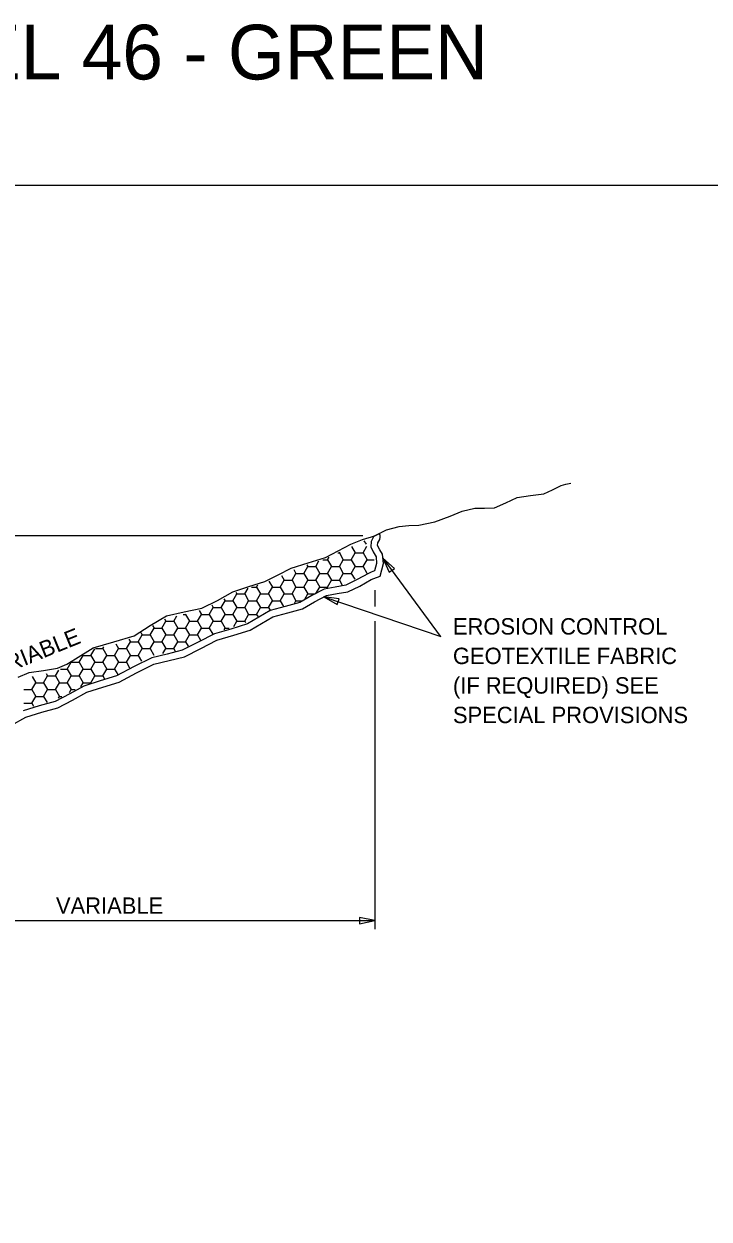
# Model space of a CAD drawing. Extents: x -439.1 to -407.9, y -458.1 to -436.2.
# Drawn here: x -424.75 to -418.48, y -447.12 to -436.2 of the extents above; entities that cross this region are included whole.
import ezdxf

# ---------------------------------------------------------------- set-up
doc = ezdxf.new("R2010")
doc.units = 0
for name, color, linetype in [('Default', 7, 'Continuous'), ('Draft_Named_Boundary', 7, 'Continuous'), ('Level 46', 7, 'Continuous')]:
    doc.layers.add(name, color=color, linetype=linetype)

msp = doc.modelspace()

# ---------------------------------------------------------------- linework, layer by layer
at = {"layer": 'Default'}
for p, q in [((-421.646, -440.877), (-427.407, -440.877)), ((-421.537, -440.877), (-421.544, -440.879)), ((-421.493, -440.855), (-421.537, -440.877)), ((-421.749, -440.976), (-421.715, -441.033)), ((-421.643, -441.033), (-421.608, -440.973)), ((-421.635, -440.923), (-421.616, -440.955)), ((-422.076, -441.158), (-422.047, -441.107)), ((-422.012, -441.096), (-421.968, -441.096)), ((-421.968, -441.096), (-421.954, -441.071)), ((-421.968, -441.096), (-421.932, -441.158)), ((-421.873, -441.033), (-421.86, -441.033)), ((-421.86, -441.033), (-421.855, -441.025)), ((-421.86, -441.033), (-421.824, -441.096)), ((-421.86, -441.158), (-421.824, -441.096)), ((-421.824, -441.096), (-421.752, -441.096)), ((-421.752, -441.096), (-421.715, -441.033)), ((-421.752, -441.096), (-421.715, -441.158)), ((-421.715, -441.033), (-421.643, -441.033)), ((-421.643, -441.033), (-421.607, -441.096)), ((-421.643, -441.158), (-421.607, -441.096)), ((-421.607, -441.096), (-421.541, -441.096)), ((-421.461, -441.081), (-420.937, -441.794)), ((-422.293, -441.283), (-422.257, -441.221)), ((-422.277, -441.186), (-422.257, -441.221)), ((-422.257, -441.221), (-422.185, -441.221)), ((-422.185, -441.221), (-422.148, -441.158)), ((-422.185, -441.221), (-422.148, -441.283)), ((-422.157, -441.144), (-422.148, -441.158)), ((-422.148, -441.158), (-422.076, -441.158)), ((-422.076, -441.158), (-422.04, -441.221)), ((-422.076, -441.283), (-422.04, -441.221)), ((-422.04, -441.221), (-421.968, -441.221)), ((-421.968, -441.221), (-421.932, -441.158)), ((-421.968, -441.221), (-421.932, -441.283)), ((-421.932, -441.158), (-421.86, -441.158)), ((-421.86, -441.158), (-421.824, -441.221)), ((-421.86, -441.283), (-421.824, -441.221)), ((-421.824, -441.221), (-421.752, -441.221)), ((-421.752, -441.221), (-421.715, -441.158)), ((-421.752, -441.221), (-421.72, -441.275)), ((-421.715, -441.158), (-421.643, -441.158)), ((-421.643, -441.158), (-421.608, -441.219)), ((-422.618, -441.346), (-422.606, -441.326)), ((-422.504, -441.292), (-422.473, -441.346)), ((-422.401, -441.346), (-422.365, -441.283)), ((-422.39, -441.24), (-422.365, -441.283)), ((-422.365, -441.283), (-422.293, -441.283)), ((-422.293, -441.283), (-422.257, -441.346)), ((-422.185, -441.346), (-422.148, -441.283)), ((-422.148, -441.283), (-422.076, -441.283)), ((-422.076, -441.283), (-422.04, -441.346)), ((-421.968, -441.346), (-421.932, -441.283)), ((-421.932, -441.283), (-421.86, -441.283)), ((-421.86, -441.283), (-421.834, -441.328)), ((-422.834, -441.471), (-422.798, -441.408)), ((-422.806, -441.394), (-422.798, -441.408)), ((-422.798, -441.408), (-422.726, -441.408)), ((-422.726, -441.408), (-422.696, -441.356)), ((-422.726, -441.408), (-422.69, -441.471)), ((-422.664, -441.346), (-422.618, -441.346)), ((-422.618, -441.346), (-422.581, -441.408)), ((-422.618, -441.471), (-422.581, -441.408)), ((-422.581, -441.408), (-422.509, -441.408)), ((-422.509, -441.408), (-422.473, -441.346)), ((-422.509, -441.408), (-422.473, -441.471)), ((-422.473, -441.346), (-422.401, -441.346)), ((-422.401, -441.346), (-422.365, -441.408)), ((-422.401, -441.471), (-422.365, -441.408)), ((-422.365, -441.408), (-422.293, -441.408)), ((-422.293, -441.408), (-422.257, -441.346)), ((-422.293, -441.408), (-422.257, -441.471)), ((-422.257, -441.346), (-422.185, -441.346)), ((-422.185, -441.346), (-422.148, -441.408)), ((-422.177, -441.457), (-422.148, -441.408)), ((-422.148, -441.408), (-422.08, -441.408)), ((-422.075, -441.406), (-422.04, -441.346)), ((-422.04, -441.346), (-421.968, -441.346)), ((-422.001, -441.435), (-420.932, -441.798)), ((-421.968, -441.346), (-421.965, -441.35)), ((-421.537, -441.373), (-421.537, -441.524)), ((-423.051, -441.596), (-423.015, -441.533)), ((-423.028, -441.509), (-423.015, -441.533)), ((-423.015, -441.533), (-422.942, -441.533)), ((-422.942, -441.533), (-422.906, -441.471)), ((-422.942, -441.533), (-422.906, -441.596)), ((-422.917, -441.452), (-422.906, -441.471)), ((-422.906, -441.471), (-422.834, -441.471)), ((-422.834, -441.471), (-422.798, -441.533)), ((-422.834, -441.596), (-422.798, -441.533)), ((-422.798, -441.533), (-422.726, -441.533)), ((-422.726, -441.533), (-422.69, -441.471)), ((-422.726, -441.533), (-422.69, -441.596)), ((-422.69, -441.471), (-422.618, -441.471)), ((-422.618, -441.471), (-422.581, -441.533)), ((-422.618, -441.596), (-422.581, -441.533)), ((-422.581, -441.533), (-422.509, -441.533)), ((-422.509, -441.533), (-422.473, -441.471)), ((-422.509, -441.533), (-422.491, -441.564)), ((-422.473, -441.471), (-422.401, -441.471)), ((-422.401, -441.471), (-422.37, -441.525)), ((-422.271, -441.496), (-422.257, -441.471)), ((-422.257, -441.471), (-422.204, -441.471)), ((-423.484, -441.721), (-423.448, -441.658)), ((-423.46, -441.637), (-423.448, -441.658)), ((-423.448, -441.658), (-423.375, -441.658)), ((-423.375, -441.658), (-423.347, -441.609)), ((-423.375, -441.658), (-423.339, -441.721)), ((-423.29, -441.596), (-423.267, -441.596)), ((-423.267, -441.596), (-423.264, -441.59)), ((-423.267, -441.596), (-423.231, -441.658)), ((-423.267, -441.721), (-423.231, -441.658)), ((-423.231, -441.658), (-423.159, -441.658)), ((-423.159, -441.658), (-423.123, -441.596)), ((-423.159, -441.658), (-423.123, -441.721)), ((-423.143, -441.561), (-423.123, -441.596)), ((-423.123, -441.596), (-423.051, -441.596)), ((-423.051, -441.596), (-423.015, -441.658)), ((-423.051, -441.721), (-423.015, -441.658)), ((-423.015, -441.658), (-422.942, -441.658)), ((-422.942, -441.658), (-422.906, -441.596)), ((-422.942, -441.658), (-422.906, -441.721)), ((-422.906, -441.596), (-422.834, -441.596)), ((-422.834, -441.596), (-422.798, -441.658)), ((-422.826, -441.707), (-422.798, -441.658)), ((-422.798, -441.658), (-422.726, -441.658)), ((-422.726, -441.658), (-422.69, -441.596)), ((-422.726, -441.658), (-422.718, -441.671)), ((-422.69, -441.596), (-422.618, -441.596)), ((-422.618, -441.596), (-422.604, -441.619)), ((-421.537, -441.657), (-421.537, -444.473)), ((-423.678, -441.76), (-423.664, -441.783)), ((-423.592, -441.783), (-423.556, -441.721)), ((-423.569, -441.698), (-423.556, -441.721)), ((-423.556, -441.721), (-423.484, -441.721)), ((-423.484, -441.721), (-423.448, -441.783)), ((-423.375, -441.783), (-423.339, -441.721)), ((-423.339, -441.721), (-423.267, -441.721)), ((-423.267, -441.721), (-423.231, -441.783)), ((-423.159, -441.783), (-423.123, -441.721)), ((-423.123, -441.721), (-423.051, -441.721)), ((-423.051, -441.721), (-423.019, -441.776)), ((-422.915, -441.737), (-422.906, -441.721)), ((-422.906, -441.721), (-422.868, -441.721)), ((-423.905, -441.866), (-423.881, -441.908)), ((-423.808, -441.908), (-423.772, -441.846)), ((-423.787, -441.821), (-423.772, -441.846)), ((-423.772, -441.846), (-423.7, -441.846)), ((-423.7, -441.846), (-423.664, -441.783)), ((-423.7, -441.846), (-423.664, -441.908)), ((-423.664, -441.783), (-423.592, -441.783)), ((-423.592, -441.783), (-423.556, -441.846)), ((-423.592, -441.908), (-423.556, -441.846)), ((-423.556, -441.846), (-423.484, -441.846)), ((-423.484, -441.846), (-423.448, -441.783)), ((-423.484, -441.846), (-423.448, -441.908)), ((-423.448, -441.783), (-423.375, -441.783)), ((-423.375, -441.783), (-423.339, -441.846)), ((-423.375, -441.908), (-423.339, -441.846)), ((-423.339, -441.846), (-423.267, -441.846)), ((-423.267, -441.846), (-423.231, -441.783)), ((-423.267, -441.846), (-423.244, -441.887)), ((-423.231, -441.783), (-423.159, -441.783)), ((-423.159, -441.783), (-423.131, -441.831)), ((-424.241, -442.033), (-424.205, -441.971)), ((-424.208, -441.967), (-424.205, -441.971)), ((-424.205, -441.971), (-424.133, -441.971)), ((-424.133, -441.971), (-424.098, -441.91)), ((-424.133, -441.971), (-424.097, -442.033)), ((-424.091, -441.908), (-424.025, -441.908)), ((-424.025, -441.908), (-424.015, -441.891)), ((-424.025, -441.908), (-423.989, -441.971)), ((-424.025, -442.033), (-423.989, -441.971)), ((-423.989, -441.971), (-423.917, -441.971)), ((-423.917, -441.971), (-423.881, -441.908)), ((-423.917, -441.971), (-423.881, -442.033)), ((-423.881, -441.908), (-423.808, -441.908)), ((-423.808, -441.908), (-423.772, -441.971)), ((-423.808, -442.033), (-423.772, -441.971)), ((-423.772, -441.971), (-423.7, -441.971)), ((-423.7, -441.971), (-423.664, -441.908)), ((-423.7, -441.971), (-423.669, -442.024)), ((-423.664, -441.908), (-423.592, -441.908)), ((-423.592, -441.908), (-423.557, -441.968)), ((-423.474, -441.954), (-423.448, -441.908)), ((-423.448, -441.908), (-423.375, -441.908)), ((-423.375, -441.908), (-423.361, -441.934)), ((-424.412, -442.096), (-424.35, -442.096)), ((-424.35, -442.096), (-424.314, -442.033)), ((-424.35, -442.096), (-424.314, -442.158)), ((-424.313, -442.033), (-424.241, -442.033)), ((-424.241, -442.033), (-424.205, -442.096)), ((-424.241, -442.158), (-424.205, -442.096)), ((-424.205, -442.096), (-424.133, -442.096)), ((-424.133, -442.096), (-424.097, -442.033)), ((-424.133, -442.096), (-424.097, -442.158)), ((-424.097, -442.033), (-424.025, -442.033)), ((-424.025, -442.033), (-423.989, -442.096)), ((-424.025, -442.158), (-423.989, -442.096)), ((-423.989, -442.096), (-423.917, -442.096)), ((-423.917, -442.096), (-423.881, -442.033)), ((-423.917, -442.096), (-423.888, -442.145)), ((-423.881, -442.033), (-423.808, -442.033)), ((-423.808, -442.033), (-423.779, -442.085)), ((-424.672, -442.162), (-424.638, -442.221)), ((-424.566, -442.221), (-424.53, -442.158)), ((-424.542, -442.137), (-424.53, -442.158)), ((-424.53, -442.158), (-424.458, -442.158)), ((-424.458, -442.158), (-424.427, -442.105)), ((-424.458, -442.158), (-424.422, -442.221)), ((-424.35, -442.221), (-424.314, -442.158)), ((-424.314, -442.158), (-424.241, -442.158)), ((-424.241, -442.158), (-424.205, -442.221)), ((-424.133, -442.22), (-424.097, -442.158)), ((-424.097, -442.158), (-424.025, -442.158)), ((-424.025, -442.158), (-424.009, -442.185)), ((-424.747, -442.283), (-424.674, -442.283)), ((-424.674, -442.283), (-424.638, -442.221)), ((-424.674, -442.283), (-424.638, -442.346)), ((-424.638, -442.221), (-424.566, -442.221)), ((-424.566, -442.221), (-424.53, -442.283)), ((-424.566, -442.346), (-424.53, -442.283)), ((-424.53, -442.283), (-424.458, -442.283)), ((-424.458, -442.283), (-424.422, -442.221)), ((-424.458, -442.283), (-424.422, -442.346)), ((-424.422, -442.221), (-424.35, -442.221)), ((-424.35, -442.221), (-424.314, -442.283)), ((-424.329, -442.31), (-424.314, -442.283)), ((-424.314, -442.283), (-424.277, -442.283)), ((-424.226, -442.257), (-424.205, -442.221)), ((-424.205, -442.221), (-424.134, -442.221)), ((-424.747, -442.408), (-424.674, -442.408)), ((-424.674, -442.408), (-424.638, -442.346)), ((-424.674, -442.408), (-424.659, -442.434)), ((-424.638, -442.346), (-424.566, -442.346)), ((-424.566, -442.346), (-424.534, -442.402)), ((-424.431, -442.363), (-424.422, -442.346)), ((-424.422, -442.346), (-424.399, -442.346)), ((-426.224, -444.395), (-421.537, -444.395))]:
    msp.add_line(p, q, dxfattribs=at)
for points in [[(-421.537, -440.877), (-421.429, -440.823), (-421.314, -440.791), (-421.224, -440.784), (-421.134, -440.78), (-420.988, -440.75), (-420.847, -440.697), (-420.736, -440.652), (-420.621, -440.626), (-420.531, -440.626), (-420.442, -440.62), (-420.338, -440.576), (-420.234, -440.526), (-420.112, -440.509), (-419.99, -440.492), (-419.911, -440.456), (-419.832, -440.418), (-419.788, -440.405), (-419.742, -440.396)], [(-424.8, -442.169), (-424.697, -442.127), (-424.567, -442.109), (-424.438, -442.088), (-424.354, -442.051), (-424.275, -442.001), (-424.114, -441.901), (-423.925, -441.847), (-423.737, -441.792), (-423.59, -441.698), (-423.441, -441.609), (-423.28, -441.573), (-423.117, -441.54), (-422.975, -441.468), (-422.835, -441.39), (-422.688, -441.342), (-422.541, -441.296), (-422.421, -441.235), (-422.302, -441.174), (-422.145, -441.124), (-421.988, -441.075), (-421.871, -441.016), (-421.755, -440.955), (-421.648, -440.911), (-421.537, -440.877)], [(-421.544, -440.879), (-421.569, -440.93), (-421.573, -440.978), (-421.55, -441.023), (-421.523, -441.068), (-421.519, -441.129), (-421.539, -441.198)], [(-421.491, -440.912), (-421.486, -440.89), (-421.487, -440.873), (-421.493, -440.855)], [(-421.488, -441.245), (-421.456, -441.13), (-421.465, -441.045), (-421.49, -441.005), (-421.512, -440.965), (-421.507, -440.942), (-421.491, -440.912)], [(-421.539, -441.198), (-421.568, -441.209), (-421.595, -441.221), (-421.697, -441.278), (-421.8, -441.328), (-421.9, -441.346), (-421.999, -441.364), (-422.111, -441.423), (-422.222, -441.488), (-422.357, -441.525), (-422.493, -441.561), (-422.598, -441.621), (-422.702, -441.683), (-422.852, -441.73), (-423.004, -441.772), (-423.151, -441.849), (-423.297, -441.924), (-423.437, -441.959), (-423.577, -441.992), (-423.738, -442.071), (-423.898, -442.156), (-424.048, -442.203), (-424.197, -442.251), (-424.327, -442.322), (-424.459, -442.391), (-424.606, -442.433), (-424.753, -442.477)], [(-424.86, -442.607), (-424.729, -442.534), (-424.583, -442.491), (-424.435, -442.449), (-424.303, -442.38), (-424.172, -442.308), (-424.023, -442.26), (-423.874, -442.214), (-423.716, -442.13), (-423.557, -442.051), (-423.416, -442.018), (-423.276, -441.983), (-423.129, -441.907), (-422.981, -441.83), (-422.827, -441.787), (-422.676, -441.74), (-422.573, -441.678), (-422.469, -441.618), (-422.333, -441.582), (-422.197, -441.545), (-422.089, -441.481), (-421.979, -441.423), (-421.881, -441.405), (-421.782, -441.388), (-421.674, -441.337), (-421.569, -441.277), (-421.544, -441.267), (-421.488, -441.245)]]:
    msp.add_lwpolyline(points, dxfattribs=at)
for points in [[(-421.356, -441.176), (-421.461, -441.081), (-421.403, -441.21)], [(-421.356, -441.176), (-421.461, -441.081), (-421.403, -441.21)], [(-421.861, -441.452), (-422.001, -441.435), (-421.879, -441.506)], [(-421.861, -441.452), (-422.001, -441.435), (-421.879, -441.506)], [(-421.675, -444.424), (-421.537, -444.395), (-421.675, -444.366)]]:
    msp.add_lwpolyline(points, close=True, dxfattribs=at)
at = {"layer": 'Draft_Named_Boundary'}
msp.add_lwpolyline([(-439.109, -458.051), (-407.859, -458.051), (-407.859, -437.676), (-439.109, -437.676)], close=True, dxfattribs=at)

# ---------------------------------------------------------------- texts
at = {"layer": 'Default'}
for s, p in [('EROSION CONTROL ', (-420.821, -441.78)), ('GEOTEXTILE FABRIC ', (-420.821, -442.05)), ('(IF REQUIRED) SEE ', (-420.821, -442.32)), ('SPECIAL PROVISIONS', (-420.821, -442.59)), ('VARIABLE', (-424.453, -444.333))]:
    msp.add_text(s, height=0.15, dxfattribs=at).set_placement(p)
msp.add_text('VARIABLE', height=0.15, rotation=22, dxfattribs=at).set_placement((-425.125, -442.222))
at = {"layer": 'Level 46'}
msp.add_text('METRIC - LEVEL 46 - GREEN', height=0.5, dxfattribs=at).set_placement((-429.642, -436.705))

doc.saveas('drawing.dxf')
